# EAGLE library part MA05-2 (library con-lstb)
PIN HEADER
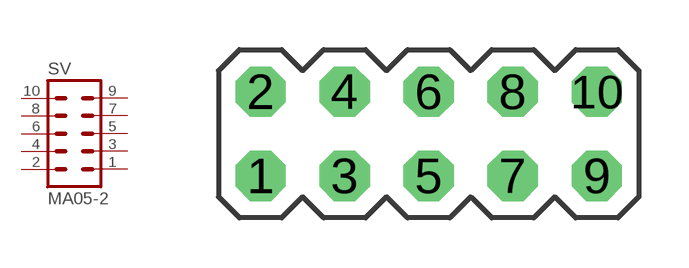
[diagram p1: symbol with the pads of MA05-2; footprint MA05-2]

Designator prefix SV

## MA05-2 (OC_FARNELL: unknown; OC_NEWARK: unknown)  [MA05-2]
1  1  pas
2  2  pas
3  3  pas
4  4  pas
5  5  pas
6  6  pas
7  7  pas
8  8  pas
9  9  pas
10  10  pas

## Footprint MA05-2 (pad centres in mm)
PIN HEADER
drill 1.016 octagon: 1 -5.08,-1.27; 2 -5.08,1.27; 3 -2.54,-1.27; 4 -2.54,1.27; 5 0,-1.27; 6 0,1.27; 7 2.54,-1.27; 8 2.54,1.27; 9 5.08,-1.27; 10 5.08,1.27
